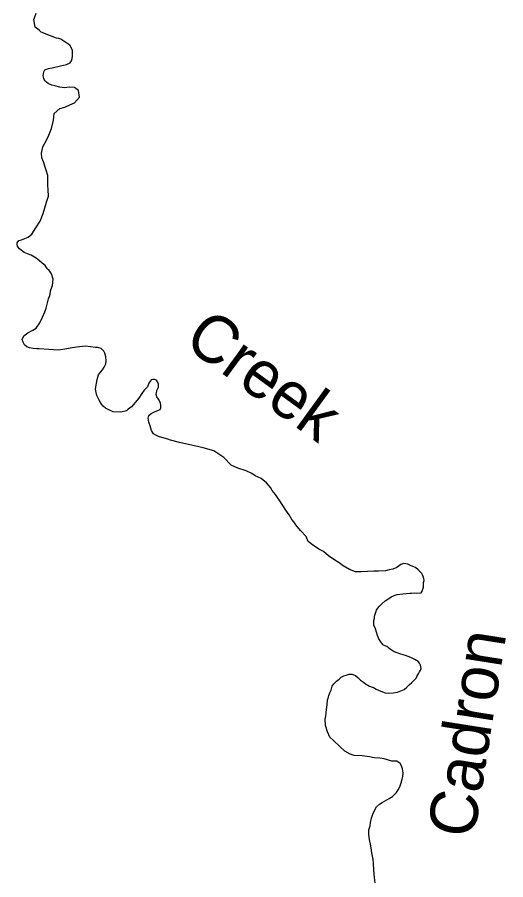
# Model space of a CAD drawing. Extents: x 31699 to 244310, y -8841 to 11474.
# Drawn here: x 102637 to 103000, y 2754 to 3394 of the extents above; entities that cross this region are included whole.
import ezdxf

# ---------------------------------------------------------------- set-up
doc = ezdxf.new("R2010")
doc.units = 0
doc.layers.add('R_Draft', color=7, linetype='Continuous')
doc.layers.add('R_Logo', color=7, linetype='Continuous')

msp = doc.modelspace()

# ---------------------------------------------------------------- linework, layer by layer
at = {"layer": 'R_Logo'}
for points in [[(102656.27, 3352.5), (102656.52, 3353.98), (102657.36, 3355.46), (102660.14, 3356.44), (102662.74, 3356.74), (102668.98, 3358.44), (102673.43, 3359.31), (102676.14, 3360.69), (102677.12, 3362.17), (102677.76, 3363.79), (102677.94, 3365.46), (102678.03, 3367.93), (102677.93, 3370.07), (102675.81, 3373.57), (102672.85, 3375.6), (102669.35, 3378.15), (102667.87, 3378.59), (102666.14, 3378.77), (102661.58, 3380.57), (102654.54, 3383.26), (102653.05, 3384.91), (102650.15, 3386.94), (102649.2, 3392.73), (102649.64, 3394.07), (102650.99, 3397.37)], [(102656.27, 3352.5), (102656.52, 3353.98), (102657.36, 3355.46), (102660.14, 3356.44), (102662.74, 3356.74), (102668.98, 3358.44), (102673.43, 3359.31), (102676.14, 3360.69), (102677.12, 3362.17), (102677.76, 3363.79), (102677.94, 3365.46), (102678.03, 3367.93), (102677.93, 3370.07), (102675.81, 3373.57), (102672.85, 3375.6), (102669.35, 3378.15), (102667.87, 3378.59), (102666.14, 3378.77), (102661.58, 3380.57), (102654.54, 3383.26), (102653.05, 3384.91), (102650.15, 3386.94), (102649.2, 3392.73), (102649.64, 3394.07), (102650.99, 3397.37)], [(102696.29, 3125.52), (102697.24, 3128.81), (102698.67, 3130.97), (102700.11, 3132.66), (102701.42, 3134.55), (102702.58, 3137.17), (102702.94, 3139.38), (102702.77, 3142.32), (102701.86, 3144.98), (102701.1, 3146.43), (102699.28, 3148.34), (102696.86, 3149.17), (102694.93, 3149.28), (102691.39, 3149.69), (102687.45, 3150.23), (102680.93, 3149.33), (102676.21, 3148.72), (102673.68, 3148.29), (102667.63, 3147.12), (102653.09, 3148.24), (102651.49, 3148.21), (102648.62, 3148.5), (102645.88, 3149.06), (102644, 3149.7), (102642.18, 3151.21), (102641.15, 3153.06), (102640.59, 3155.06), (102641.74, 3157.95), (102644.65, 3160.06), (102648.48, 3162.12), (102650.86, 3163.5), (102653.6, 3167.61), (102655.67, 3171.78), (102657.34, 3175.62), (102658.23, 3178.5), (102660.06, 3185.34), (102660.96, 3187.69), (102661.89, 3191.98), (102663.11, 3195.27), (102663.44, 3199.95), (102662.25, 3203.81), (102660.27, 3206.78), (102659.39, 3207.44), (102659.12, 3207.9), (102657.49, 3210.01), (102655.33, 3211.71), (102653.3, 3213.42), (102650.87, 3215.59), (102647.24, 3217.87), (102644.49, 3218.76), (102641.88, 3219.66), (102639.72, 3221.43), (102638.64, 3222.48), (102637.55, 3223.73), (102637.14, 3224.53), (102636.86, 3225.79), (102636.91, 3226.79), (102637.95, 3228.54), (102640, 3229.24), (102645.04, 3231.19), (102647.67, 3233.37), (102650.73, 3238.16), (102653.79, 3243.08), (102656.04, 3248.59), (102657.44, 3253.02), (102658.71, 3257.04), (102660.04, 3261.47), (102659.77, 3266.21), (102659.59, 3269.75), (102659.54, 3277.02), (102658.35, 3280.75), (102656.39, 3287.13), (102655.08, 3290.11), (102654.76, 3293.45), (102655.89, 3298.14), (102658.62, 3303.12), (102660.22, 3306.95), (102662.28, 3311.93), (102663.86, 3317.96), (102664.38, 3322.84), (102668.46, 3326.71), (102672.11, 3327.77), (102676.02, 3329.3), (102679.32, 3330.89), (102683.19, 3335.15), (102682.45, 3340.15), (102679.42, 3342.24), (102675.75, 3342.45), (102673.75, 3342.22), (102671.96, 3342.13), (102668.62, 3342.48), (102664.67, 3343.42), (102662.66, 3344.05), (102660.85, 3344.69), (102659.78, 3345.15), (102658.63, 3346.33), (102657.55, 3347.11), (102656.87, 3348.24), (102656.52, 3349.04), (102656.23, 3350.9), (102656.27, 3352.5)], [(102696.29, 3125.52), (102697.24, 3128.81), (102698.67, 3130.97), (102700.11, 3132.66), (102701.42, 3134.55), (102702.58, 3137.17), (102702.94, 3139.38), (102702.77, 3142.32), (102701.86, 3144.98), (102701.1, 3146.43), (102699.28, 3148.34), (102696.86, 3149.17), (102694.93, 3149.28), (102691.39, 3149.69), (102687.45, 3150.23), (102680.93, 3149.33), (102676.21, 3148.72), (102673.68, 3148.29), (102667.63, 3147.12), (102653.09, 3148.24), (102651.49, 3148.21), (102648.62, 3148.5), (102645.88, 3149.06), (102644, 3149.7), (102642.18, 3151.21), (102641.15, 3153.06), (102640.59, 3155.06), (102641.74, 3157.95), (102644.65, 3160.06), (102648.48, 3162.12), (102650.86, 3163.5), (102653.6, 3167.61), (102655.67, 3171.78), (102657.34, 3175.62), (102658.23, 3178.5), (102660.06, 3185.34), (102660.96, 3187.69), (102661.89, 3191.98), (102663.11, 3195.27), (102663.44, 3199.95), (102662.25, 3203.81), (102660.27, 3206.78), (102659.39, 3207.44), (102659.12, 3207.9), (102657.49, 3210.01), (102655.33, 3211.71), (102653.3, 3213.42), (102650.87, 3215.59), (102647.24, 3217.87), (102644.49, 3218.76), (102641.88, 3219.66), (102639.72, 3221.43), (102638.64, 3222.48), (102637.55, 3223.73), (102637.14, 3224.53), (102636.86, 3225.79), (102636.91, 3226.79), (102637.95, 3228.54), (102640, 3229.24), (102645.04, 3231.19), (102647.67, 3233.37), (102650.73, 3238.16), (102653.79, 3243.08), (102656.04, 3248.59), (102657.44, 3253.02), (102658.71, 3257.04), (102660.04, 3261.47), (102659.77, 3266.21), (102659.59, 3269.75), (102659.54, 3277.02), (102658.35, 3280.75), (102656.39, 3287.13), (102655.08, 3290.11), (102654.76, 3293.45), (102655.89, 3298.14), (102658.62, 3303.12), (102660.22, 3306.95), (102662.28, 3311.93), (102663.86, 3317.96), (102664.38, 3322.84), (102668.46, 3326.71), (102672.11, 3327.77), (102676.02, 3329.3), (102679.32, 3330.89), (102683.19, 3335.15), (102682.45, 3340.15), (102679.42, 3342.24), (102675.75, 3342.45), (102673.75, 3342.22), (102671.96, 3342.13), (102668.62, 3342.48), (102664.67, 3343.42), (102662.66, 3344.05), (102660.85, 3344.69), (102659.78, 3345.15), (102658.63, 3346.33), (102657.55, 3347.11), (102656.87, 3348.24), (102656.52, 3349.04), (102656.23, 3350.9), (102656.27, 3352.5)], [(102932.74, 2985.83), (102929.65, 2987.18), (102927.03, 2988.41), (102924.16, 2988.77), (102921.97, 2988), (102919, 2985.88), (102916.03, 2984.5), (102913.17, 2983.99), (102910.38, 2983.35), (102905.25, 2983), (102901.78, 2983.08), (102897.12, 2982.94), (102892.33, 2982.67), (102888.13, 2982.67), (102883.7, 2984.34), (102879.13, 2987.01), (102875.96, 2989.37), (102872.93, 2991.32), (102868.09, 2994.59), (102864.37, 2997.67), (102860.95, 2999.42), (102860.01, 3000.07), (102857.18, 3001.83), (102853.13, 3005.18), (102851.47, 3008.96), (102847.21, 3013.37), (102843.95, 3017.39), (102842.25, 3019.7), (102840.96, 3021.35), (102838.84, 3024.86), (102836.32, 3028.43), (102834.2, 3031.94), (102831.4, 3036.17), (102830.79, 3036.96), (102828.74, 3040), (102826.37, 3043.03), (102825, 3045.15), (102822.08, 3048.71), (102818.17, 3051.93), (102813.67, 3053.86), (102811.05, 3055.56), (102807.02, 3057.5), (102800.86, 3059.47), (102795.82, 3061.87), (102790.27, 3067.46), (102782.93, 3072.42), (102774.9, 3074.7), (102771.89, 3075.46), (102757.38, 3078.58), (102750.69, 3080.48), (102748.81, 3081.18), (102744.19, 3082.45), (102741.71, 3083.21), (102739.9, 3084.05), (102738.02, 3085.16), (102736.52, 3087.61), (102735.53, 3091.06), (102734.69, 3093.86), (102734.25, 3096.65), (102734.55, 3098.8), (102736.26, 3100.29), (102738.91, 3101.4), (102741.76, 3102.58), (102742.94, 3103.27), (102743.46, 3104.48), (102743.64, 3105.88), (102743.34, 3108.08), (102741.76, 3110.79), (102740.54, 3112.51), (102740.11, 3114.24), (102740.22, 3115.85), (102740.79, 3117.66), (102741.83, 3119.68), (102741.79, 3122.08), (102741.1, 3123.67), (102740.22, 3124.93), (102738.88, 3125.51), (102737.68, 3125.42), (102736.48, 3125.07), (102734.72, 3122.71), (102733.69, 3120.09), (102731.26, 3117.58), (102729.5, 3115.01), (102727.09, 3111.57), (102721.72, 3105.21), (102719.22, 3103.37), (102718.03, 3102.28), (102713.78, 3101.15), (102708.25, 3101.33), (102705.03, 3102.89), (102702.48, 3104.05), (102700.65, 3105.62), (102699.36, 3107.21), (102697.72, 3110.12), (102696, 3113.43), (102695.5, 3115.76), (102695, 3118.23), (102695.48, 3121.31), (102695.66, 3122.78), (102696.29, 3125.52)], [(102932.74, 2985.83), (102929.65, 2987.18), (102927.03, 2988.41), (102924.16, 2988.77), (102921.97, 2988), (102919, 2985.88), (102916.03, 2984.5), (102913.17, 2983.99), (102910.38, 2983.35), (102905.25, 2983), (102901.78, 2983.08), (102897.12, 2982.94), (102892.33, 2982.67), (102888.13, 2982.67), (102883.7, 2984.34), (102879.13, 2987.01), (102875.96, 2989.37), (102872.93, 2991.32), (102868.09, 2994.59), (102864.37, 2997.67), (102860.95, 2999.42), (102860.01, 3000.07), (102857.18, 3001.83), (102853.13, 3005.18), (102851.47, 3008.96), (102847.21, 3013.37), (102843.95, 3017.39), (102842.25, 3019.7), (102840.96, 3021.35), (102838.84, 3024.86), (102836.32, 3028.43), (102834.2, 3031.94), (102831.4, 3036.17), (102830.79, 3036.96), (102828.74, 3040), (102826.37, 3043.03), (102825, 3045.15), (102822.08, 3048.71), (102818.17, 3051.93), (102813.67, 3053.86), (102811.05, 3055.56), (102807.02, 3057.5), (102800.86, 3059.47), (102795.82, 3061.87), (102790.27, 3067.46), (102782.93, 3072.42), (102774.9, 3074.7), (102771.89, 3075.46), (102757.38, 3078.58), (102750.69, 3080.48), (102748.81, 3081.18), (102744.19, 3082.45), (102741.71, 3083.21), (102739.9, 3084.05), (102738.02, 3085.16), (102736.52, 3087.61), (102735.53, 3091.06), (102734.69, 3093.86), (102734.25, 3096.65), (102734.55, 3098.8), (102736.26, 3100.29), (102738.91, 3101.4), (102741.76, 3102.58), (102742.94, 3103.27), (102743.46, 3104.48), (102743.64, 3105.88), (102743.34, 3108.08), (102741.76, 3110.79), (102740.54, 3112.51), (102740.11, 3114.24), (102740.22, 3115.85), (102740.79, 3117.66), (102741.83, 3119.68), (102741.79, 3122.08), (102741.1, 3123.67), (102740.22, 3124.93), (102738.88, 3125.51), (102737.68, 3125.42), (102736.48, 3125.07), (102734.72, 3122.71), (102733.69, 3120.09), (102731.26, 3117.58), (102729.5, 3115.01), (102727.09, 3111.57), (102721.72, 3105.21), (102719.22, 3103.37), (102718.03, 3102.28), (102713.78, 3101.15), (102708.25, 3101.33), (102705.03, 3102.89), (102702.48, 3104.05), (102700.65, 3105.62), (102699.36, 3107.21), (102697.72, 3110.12), (102696, 3113.43), (102695.5, 3115.76), (102695, 3118.23), (102695.48, 3121.31), (102695.66, 3122.78), (102696.29, 3125.52)], [(102937.41, 2981.35), (102936.08, 2982.89), (102934.85, 2984.15), (102932.74, 2985.83)], [(102937.41, 2981.35), (102936.08, 2982.89), (102934.85, 2984.15), (102932.74, 2985.83)], [(102933.76, 2966.74), (102936.89, 2966.99), (102937.73, 2968.34), (102938.24, 2969.68), (102938.62, 2971.29), (102938.83, 2974.77), (102939.08, 2976.24), (102938.71, 2978.71), (102937.95, 2980.3), (102937.41, 2981.35)], [(102933.76, 2966.74), (102936.89, 2966.99), (102937.73, 2968.34), (102938.24, 2969.68), (102938.62, 2971.29), (102938.83, 2974.77), (102939.08, 2976.24), (102938.71, 2978.71), (102937.95, 2980.3), (102937.41, 2981.35)], [(102865.79, 2868.6), (102865.65, 2873.08), (102866.02, 2875.49), (102866.61, 2880.3), (102867.09, 2883.92), (102867.44, 2887.46), (102867.82, 2888.8), (102868.32, 2890.88), (102869.02, 2892.83), (102869.99, 2894.85), (102870.88, 2897.66), (102871.99, 2899.55), (102874.16, 2901.45), (102876.07, 2903.02), (102877.64, 2904.45), (102879.56, 2905.41), (102881.36, 2905.9), (102883.54, 2906.61), (102885.34, 2906.7), (102888.09, 2905.67), (102890.18, 2903.9), (102892.01, 2902.26), (102894.16, 2900.76), (102896.26, 2898.92), (102897.33, 2898.34), (102898.47, 2897.82), (102900.08, 2897.24), (102901.62, 2896.67), (102903.64, 2895.43), (102907.13, 2893.94), (102910.28, 2892.86), (102912.41, 2892.62), (102916.28, 2892.75), (102919.27, 2893.33), (102921.92, 2894.3), (102924.24, 2895.27), (102926.41, 2896.98), (102928.18, 2898.81), (102930.09, 2900.37), (102933.17, 2903.76), (102933.69, 2904.77), (102934.6, 2906.12), (102935.32, 2907.26), (102935.71, 2908.27), (102936.49, 2909.55), (102936.87, 2910.76), (102936.56, 2913.29), (102935.74, 2914.68), (102934.72, 2916), (102932.37, 2917.5), (102929.21, 2918.92), (102925.33, 2920.4), (102921.84, 2921.48), (102919.03, 2922.44), (102917.02, 2923.21), (102913.86, 2925.1), (102911.56, 2927.27), (102908.88, 2928.23), (102907.59, 2929.88), (102905.41, 2932.79), (102904.57, 2935.24), (102903.73, 2937.9), (102903.03, 2940.3), (102901.92, 2943.08), (102901.74, 2946.42), (102902.18, 2948.3), (102902.42, 2949.77), (102902.92, 2951.85), (102903.75, 2954.26), (102904.66, 2955.68), (102905.71, 2956.9), (102907.75, 2958.8), (102910.18, 2961.17), (102912.3, 2962.27), (102914.6, 2963.98), (102916.92, 2965.02), (102919.18, 2965.72), (102923.3, 2966.38), (102925.83, 2966.55), (102928.62, 2966.8), (102929.82, 2966.82), (102931.75, 2966.91), (102933.76, 2966.74)], [(102865.79, 2868.6), (102865.65, 2873.08), (102866.02, 2875.49), (102866.61, 2880.3), (102867.09, 2883.92), (102867.44, 2887.46), (102867.82, 2888.8), (102868.32, 2890.88), (102869.02, 2892.83), (102869.99, 2894.85), (102870.88, 2897.66), (102871.99, 2899.55), (102874.16, 2901.45), (102876.07, 2903.02), (102877.64, 2904.45), (102879.56, 2905.41), (102881.36, 2905.9), (102883.54, 2906.61), (102885.34, 2906.7), (102888.09, 2905.67), (102890.18, 2903.9), (102892.01, 2902.26), (102894.16, 2900.76), (102896.26, 2898.92), (102897.33, 2898.34), (102898.47, 2897.82), (102900.08, 2897.24), (102901.62, 2896.67), (102903.64, 2895.43), (102907.13, 2893.94), (102910.28, 2892.86), (102912.41, 2892.62), (102916.28, 2892.75), (102919.27, 2893.33), (102921.92, 2894.3), (102924.24, 2895.27), (102926.41, 2896.98), (102928.18, 2898.81), (102930.09, 2900.37), (102933.17, 2903.76), (102933.69, 2904.77), (102934.6, 2906.12), (102935.32, 2907.26), (102935.71, 2908.27), (102936.49, 2909.55), (102936.87, 2910.76), (102936.56, 2913.29), (102935.74, 2914.68), (102934.72, 2916), (102932.37, 2917.5), (102929.21, 2918.92), (102925.33, 2920.4), (102921.84, 2921.48), (102919.03, 2922.44), (102917.02, 2923.21), (102913.86, 2925.1), (102911.56, 2927.27), (102908.88, 2928.23), (102907.59, 2929.88), (102905.41, 2932.79), (102904.57, 2935.24), (102903.73, 2937.9), (102903.03, 2940.3), (102901.92, 2943.08), (102901.74, 2946.42), (102902.18, 2948.3), (102902.42, 2949.77), (102902.92, 2951.85), (102903.75, 2954.26), (102904.66, 2955.68), (102905.71, 2956.9), (102907.75, 2958.8), (102910.18, 2961.17), (102912.3, 2962.27), (102914.6, 2963.98), (102916.92, 2965.02), (102919.18, 2965.72), (102923.3, 2966.38), (102925.83, 2966.55), (102928.62, 2966.8), (102929.82, 2966.82), (102931.75, 2966.91), (102933.76, 2966.74)], [(102902.74, 2751.7), (102902.42, 2755.57), (102901.73, 2761.43), (102901.46, 2765.97), (102901.22, 2768.91), (102900.41, 2773.84), (102899.75, 2777.77), (102899.31, 2780.3), (102898.66, 2783.89), (102898.14, 2787.62), (102898.09, 2790.96), (102899.04, 2793.92), (102899.4, 2796.59), (102900.09, 2799.81), (102900.98, 2802.63), (102901.81, 2804.44), (102903.89, 2808.01), (102905.99, 2810.18), (102908.11, 2811.42), (102913.2, 2814.17), (102915.71, 2815.87), (102918.73, 2818.73), (102919.97, 2820.68), (102921.13, 2822.97), (102922.15, 2825.92), (102922.98, 2828.74), (102923.35, 2830.55), (102923.57, 2833.29), (102923, 2836.29), (102922.43, 2838.62), (102921.4, 2840.27), (102918.91, 2842.03), (102915.24, 2841.98), (102909.55, 2843.76), (102906.15, 2844.18), (102902.01, 2844.38), (102898.6, 2845.13), (102893.12, 2845.98), (102887.19, 2846.16), (102884.31, 2847.12), (102880.27, 2849.46), (102876.42, 2853.01), (102871.82, 2857.28), (102869.05, 2859.77), (102867.26, 2863.68), (102865.79, 2868.6)], [(102902.74, 2751.7), (102902.42, 2755.57), (102901.73, 2761.43), (102901.46, 2765.97), (102901.22, 2768.91), (102900.41, 2773.84), (102899.75, 2777.77), (102899.31, 2780.3), (102898.66, 2783.89), (102898.14, 2787.62), (102898.09, 2790.96), (102899.04, 2793.92), (102899.4, 2796.59), (102900.09, 2799.81), (102900.98, 2802.63), (102901.81, 2804.44), (102903.89, 2808.01), (102905.99, 2810.18), (102908.11, 2811.42), (102913.2, 2814.17), (102915.71, 2815.87), (102918.73, 2818.73), (102919.97, 2820.68), (102921.13, 2822.97), (102922.15, 2825.92), (102922.98, 2828.74), (102923.35, 2830.55), (102923.57, 2833.29), (102923, 2836.29), (102922.43, 2838.62), (102921.4, 2840.27), (102918.91, 2842.03), (102915.24, 2841.98), (102909.55, 2843.76), (102906.15, 2844.18), (102902.01, 2844.38), (102898.6, 2845.13), (102893.12, 2845.98), (102887.19, 2846.16), (102884.31, 2847.12), (102880.27, 2849.46), (102876.42, 2853.01), (102871.82, 2857.28), (102869.05, 2859.77), (102867.26, 2863.68), (102865.79, 2868.6)]]:
    msp.add_lwpolyline(points, dxfattribs=at)

# ---------------------------------------------------------------- texts
at = {"layer": 'R_Draft'}
for s, rotation, p in [('Creek', 324, (102759.24, 3151.45)), ('Cadron', 81, (102976.15, 2783.84))]:
    msp.add_text(s, height=35.2, rotation=rotation, dxfattribs=at).set_placement(p)

doc.saveas('drawing.dxf')
